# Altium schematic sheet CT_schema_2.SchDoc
size 206 x 174 mm
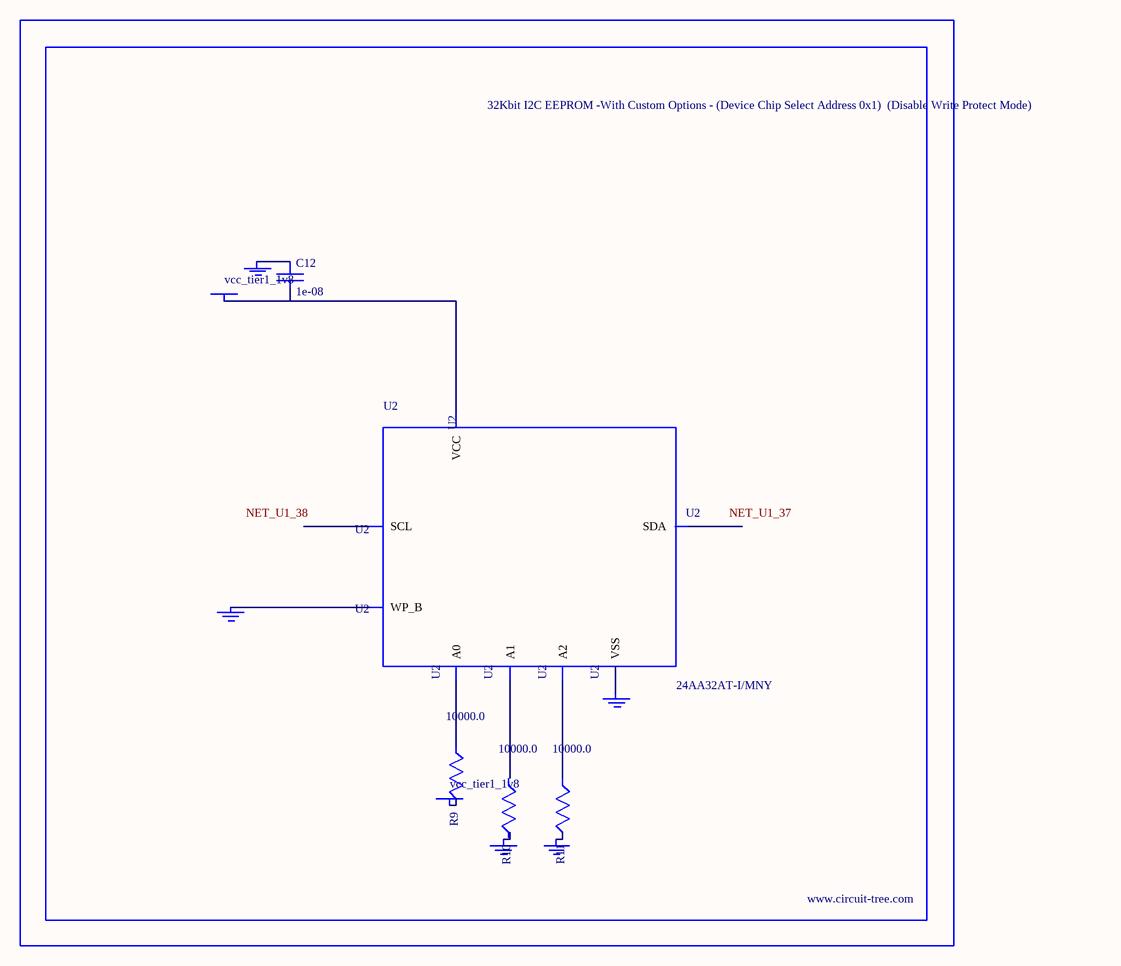
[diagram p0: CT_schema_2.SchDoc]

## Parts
BORDER1  (no value)
C12  1e-08  [C0402]
GND_INSTANCE_1_0  (no value)
GND_INSTANCE_1_1  (no value)
GND_INSTANCE_1_2  (no value)
GND_INSTANCE_1_3  (no value)
GND_INSTANCE_1_4  (no value)
POWER_INSTANCE_1_0  vcc_tier1_1v8
POWER_INSTANCE_1_1  vcc_tier1_1v8
R9  10000.0  [R0603]
R10  10000.0  [R0603]
R11  10000.0  [R0603]
U2  24AA32AT-I/MNY  [TDFN-8/6MM]

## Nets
NetC12_1: C12.1 GND_INSTANCE_1_3.0(GND)
NetC12_2: C12.2 POWER_INSTANCE_1_1.0(PWR) U2.8(VCC)
NetGND_INSTANCE_1_1_0: GND_INSTANCE_1_1.0(GND) R11.2
NetGND_INSTANCE_1_2_0: GND_INSTANCE_1_2.0(GND) U2.7(WP_B)
NetGND_INSTANCE_1_4_0: GND_INSTANCE_1_4.0(GND) U2.4(VSS)
NetPOWER_INSTANCE_1_0_0: POWER_INSTANCE_1_0.0(PWR) R9.2
NetR9_1: R9.1 U2.1(A0)
NetR11_1: R11.1 U2.3(A2)

Not connected (* = marked no-connect by the designer): GND_INSTANCE_1_0 0(GND); R10 1 2; U2 2(A1) 5(SDA) 6(SCL)

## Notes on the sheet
- Labels drawn without touching a wire or pin: NET_U1_37, NET_U1_38

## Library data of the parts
BORDER1 = BORDER_PAGE1
C12 = C0402C103K3RAC
GND_INSTANCE_1_0-GND_INSTANCE_1_4 = GND
POWER_INSTANCE_1_0 POWER_INSTANCE_1_1 = PWR
R9-R11 = RC0603JR-0710KL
